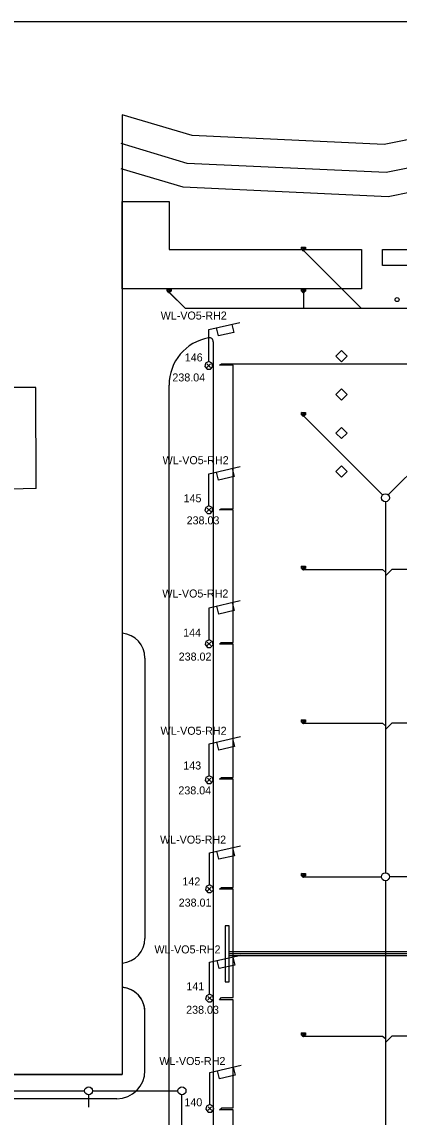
# Model space of a CAD drawing. Extents: x -264222 to -263592, y -1242345 to -1242048.
# Drawn here: x -263972 to -263924.9, y -1242184.8 to -1242047.9 of the extents above; entities that cross this region are included whole.
import ezdxf

# ---------------------------------------------------------------- set-up
doc = ezdxf.new("R2010")
doc.units = 0
for name, color, linetype in [('BOD_CISLO', 7, 'Continuous'), ('BOD_SYMBOL', 7, 'Continuous'), ('BOD_VYSKA', 7, 'Continuous'), ('KFA_2D_SITUACIA_DSP', 7, 'Continuous'), ('KFA_SO_62-1_VO_LAMPY_MERANE', 7, 'Continuous'), ('KFA_SO_62-1_VO_POPIS_LAMP_PROJEKT', 7, 'Continuous'), ('KFA_SO_62-1_VO_TRASA_KABLOV_PROJEKT', 7, 'Continuous'), ('RAM_NA_TLAC_1-500', 7, 'Continuous')]:
    doc.layers.add(name, color=color, linetype=linetype)

msp = doc.modelspace()

# ---------------------------------------------------------------- linework, layer by layer
at = {"layer": 'BOD_SYMBOL'}
for p, q in [((-263948.88, -1242091.1), (-263948.44, -1242090.66)), ((-263948.44, -1242091.1), (-263948.88, -1242090.66)), ((-263948.85, -1242109.12), (-263948.41, -1242108.68)), ((-263948.41, -1242109.12), (-263948.85, -1242108.68)), ((-263948.84, -1242125.86), (-263948.4, -1242125.42)), ((-263948.4, -1242125.86), (-263948.84, -1242125.42)), ((-263948.83, -1242142.86), (-263948.39, -1242142.42)), ((-263948.39, -1242142.86), (-263948.83, -1242142.42)), ((-263948.8, -1242156.5), (-263948.36, -1242156.05)), ((-263948.36, -1242156.5), (-263948.8, -1242156.05)), ((-263948.77, -1242170.15), (-263948.33, -1242169.71)), ((-263948.33, -1242170.15), (-263948.77, -1242169.71)), ((-263948.75, -1242183.93), (-263948.31, -1242183.49)), ((-263948.31, -1242183.93), (-263948.75, -1242183.49))]:
    msp.add_line(p, q, dxfattribs=at)
at = {"layer": 'KFA_2D_SITUACIA_DSP'}
for p, q in [((-263959.47, -1242059.53), (-263959.47, -1242179.48)), ((-263950.75, -1242062.15), (-263959.47, -1242059.53)), ((-263926.77, -1242063.25), (-263950.75, -1242062.15)), ((-263915.2, -1242060.92), (-263926.77, -1242063.25)), ((-263959.47, -1242071.38), (-263959.47, -1242070.38)), ((-263959.47, -1242070.38), (-263953.62, -1242070.38)), ((-263959.47, -1242076.38), (-263959.47, -1242071.38)), ((-263953.62, -1242070.38), (-263953.62, -1242076.38)), ((-263959.47, -1242081.31), (-263959.47, -1242076.38)), ((-263953.62, -1242076.38), (-263929.58, -1242076.38)), ((-263937.09, -1242076.38), (-263937.09, -1242076.09)), ((-263937.09, -1242076.09), (-263936.59, -1242076.09)), ((-263936.59, -1242076.38), (-263937.09, -1242076.09)), ((-263936.59, -1242076.38), (-263937.09, -1242076.09)), ((-263937.09, -1242076.09), (-263937.09, -1242076.38)), ((-263936.59, -1242076.38), (-263937.09, -1242076.38)), ((-263937.09, -1242076.38), (-263936.59, -1242076.38)), ((-263936.77, -1242076.55), (-263929.63, -1242083.7)), ((-263936.59, -1242076.09), (-263936.59, -1242076.38)), ((-263929.58, -1242076.38), (-263929.58, -1242081.31)), ((-263926.97, -1242076.38), (-263921.97, -1242076.38)), ((-263926.97, -1242078.38), (-263926.97, -1242076.38)), ((-263926.97, -1242076.38), (-263926.97, -1242076.38)), ((-263921.97, -1242078.38), (-263926.97, -1242078.38)), ((-263953.62, -1242081.31), (-263959.47, -1242081.31)), ((-263953.87, -1242081.6), (-263953.87, -1242081.31)), ((-263953.87, -1242081.31), (-263953.37, -1242081.31)), ((-263953.37, -1242081.6), (-263953.87, -1242081.31)), ((-263953.37, -1242081.6), (-263953.87, -1242081.31)), ((-263953.87, -1242081.31), (-263953.87, -1242081.6)), ((-263929.58, -1242081.31), (-263953.62, -1242081.31)), ((-263953.37, -1242081.31), (-263953.37, -1242081.6)), ((-263937.09, -1242081.6), (-263937.09, -1242081.31)), ((-263937.09, -1242081.31), (-263936.59, -1242081.31)), ((-263936.59, -1242081.6), (-263937.09, -1242081.31)), ((-263936.59, -1242081.6), (-263937.09, -1242081.31)), ((-263937.09, -1242081.31), (-263937.09, -1242081.6)), ((-263936.59, -1242081.31), (-263936.59, -1242081.6)), ((-263953.37, -1242081.6), (-263953.87, -1242081.6)), ((-263953.87, -1242081.6), (-263953.37, -1242081.6)), ((-263953.62, -1242081.7), (-263951.62, -1242083.7)), ((-263953.55, -1242081.77), (-263951.62, -1242083.7)), ((-263936.59, -1242081.6), (-263937.09, -1242081.6)), ((-263937.09, -1242081.6), (-263936.59, -1242081.6)), ((-263936.84, -1242081.8), (-263936.84, -1242083.7)), ((-263951.62, -1242083.7), (-263918.81, -1242083.7)), ((-263948.09, -1242087.9), (-263948.09, -1242241.46)), ((-263932.8, -1242089.71), (-263932.09, -1242089)), ((-263932.09, -1242089), (-263931.39, -1242089.71)), ((-263932.09, -1242089), (-263932.09, -1242089)), ((-263932.09, -1242090.41), (-263932.8, -1242089.71)), ((-263931.39, -1242089.71), (-263932.09, -1242090.41)), ((-263970.24, -1242093.63), (-263975.68, -1242093.61)), ((-263970.22, -1242106.22), (-263970.24, -1242093.63)), ((-263953.62, -1242244.46), (-263953.62, -1242093.31)), ((-263932.8, -1242094.51), (-263932.09, -1242093.8)), ((-263932.09, -1242095.21), (-263932.8, -1242094.51)), ((-263932.09, -1242093.8), (-263931.39, -1242094.51)), ((-263932.09, -1242093.8), (-263932.09, -1242093.8)), ((-263931.39, -1242094.51), (-263932.09, -1242095.21)), ((-263937.09, -1242097.05), (-263937.09, -1242096.76)), ((-263937.09, -1242096.76), (-263936.59, -1242096.76)), ((-263936.59, -1242097.05), (-263937.09, -1242096.76)), ((-263936.59, -1242097.05), (-263937.09, -1242096.76)), ((-263937.09, -1242096.76), (-263937.09, -1242097.05)), ((-263936.59, -1242097.05), (-263937.09, -1242097.05)), ((-263937.09, -1242097.05), (-263936.59, -1242097.05)), ((-263936.77, -1242097.22), (-263926.95, -1242107.05)), ((-263936.59, -1242096.76), (-263936.59, -1242097.05)), ((-263916.41, -1242097.22), (-263926.24, -1242107.05)), ((-263932.8, -1242099.31), (-263932.09, -1242098.6)), ((-263932.09, -1242098.6), (-263931.39, -1242099.31)), ((-263932.09, -1242098.6), (-263932.09, -1242098.6)), ((-263932.09, -1242100.01), (-263932.8, -1242099.31)), ((-263931.39, -1242099.31), (-263932.09, -1242100.01)), ((-263932.8, -1242104.11), (-263932.09, -1242103.4)), ((-263932.09, -1242104.81), (-263932.8, -1242104.11)), ((-263932.09, -1242103.4), (-263931.39, -1242104.11)), ((-263932.09, -1242103.4), (-263932.09, -1242103.4)), ((-263931.39, -1242104.11), (-263932.09, -1242104.81)), ((-263970.22, -1242106.22), (-263975.57, -1242106.38)), ((-263926.59, -1242107.9), (-263926.59, -1242154.25)), ((-263926.59, -1242107.9), (-263926.59, -1242154.25)), ((-263937.09, -1242116.25), (-263937.09, -1242115.96)), ((-263937.09, -1242115.96), (-263936.59, -1242115.96)), ((-263936.59, -1242116.25), (-263937.09, -1242115.96)), ((-263936.59, -1242116.25), (-263937.09, -1242115.96)), ((-263937.09, -1242115.96), (-263937.09, -1242116.25)), ((-263936.59, -1242116.25), (-263937.09, -1242116.25)), ((-263937.09, -1242116.25), (-263936.59, -1242116.25)), ((-263936.74, -1242116.35), (-263926.95, -1242116.35)), ((-263936.59, -1242115.96), (-263936.59, -1242116.25)), ((-263926.95, -1242116.35), (-263926.59, -1242116.68)), ((-263925.8, -1242116.35), (-263926.59, -1242117.15)), ((-263916.44, -1242116.35), (-263925.8, -1242116.35)), ((-263959.47, -1242124.32), (-263959.47, -1242124.32)), ((-263956.62, -1242127.42), (-263956.62, -1242162.45)), ((-263937.09, -1242135.45), (-263937.09, -1242135.16)), ((-263937.09, -1242135.16), (-263936.59, -1242135.16)), ((-263936.59, -1242135.45), (-263937.09, -1242135.16)), ((-263936.59, -1242135.45), (-263937.09, -1242135.16)), ((-263937.09, -1242135.16), (-263937.09, -1242135.45)), ((-263936.59, -1242135.45), (-263937.09, -1242135.45)), ((-263937.09, -1242135.45), (-263936.59, -1242135.45)), ((-263936.74, -1242135.55), (-263926.95, -1242135.55)), ((-263936.59, -1242135.16), (-263936.59, -1242135.45)), ((-263926.95, -1242135.55), (-263926.59, -1242135.88)), ((-263925.8, -1242135.55), (-263926.59, -1242136.35)), ((-263920.94, -1242135.55), (-263925.8, -1242135.55)), ((-263937.09, -1242154.65), (-263937.09, -1242154.36)), ((-263937.09, -1242154.36), (-263936.59, -1242154.36)), ((-263936.59, -1242154.65), (-263937.09, -1242154.36)), ((-263936.59, -1242154.65), (-263937.09, -1242154.36)), ((-263937.09, -1242154.36), (-263937.09, -1242154.65)), ((-263936.59, -1242154.65), (-263937.09, -1242154.65)), ((-263937.09, -1242154.65), (-263936.59, -1242154.65)), ((-263936.74, -1242154.75), (-263927.09, -1242154.75)), ((-263936.59, -1242154.36), (-263936.59, -1242154.65)), ((-263920.94, -1242154.75), (-263926.09, -1242154.75)), ((-263926.59, -1242155.25), (-263926.59, -1242204.25)), ((-263918.49, -1242164.13), (-263946.09, -1242164.13)), ((-263918.59, -1242164.38), (-263946.09, -1242164.38)), ((-263918.7, -1242164.63), (-263946.09, -1242164.63)), ((-263959.47, -1242165.55), (-263959.47, -1242165.55)), ((-263959.47, -1242168.58), (-263959.47, -1242168.58)), ((-263956.62, -1242178.98), (-263956.62, -1242171.65)), ((-263937.09, -1242174.55), (-263937.09, -1242174.26)), ((-263937.09, -1242174.26), (-263936.59, -1242174.26)), ((-263936.59, -1242174.55), (-263937.09, -1242174.26)), ((-263936.59, -1242174.55), (-263937.09, -1242174.26)), ((-263937.09, -1242174.26), (-263937.09, -1242174.55)), ((-263936.59, -1242174.26), (-263936.59, -1242174.55)), ((-263936.59, -1242174.55), (-263937.09, -1242174.55)), ((-263937.09, -1242174.55), (-263936.59, -1242174.55)), ((-263936.74, -1242174.65), (-263926.95, -1242174.65)), ((-263926.95, -1242174.65), (-263926.59, -1242174.98)), ((-263925.8, -1242174.65), (-263926.59, -1242175.45)), ((-263920.94, -1242174.65), (-263925.8, -1242174.65)), ((-264131.57, -1242179.48), (-263959.47, -1242179.48)), ((-263959.47, -1242179.48), (-264131.57, -1242179.48)), ((-263959.47, -1242179.48), (-264077.23, -1242179.48)), ((-263956.62, -1242178.98), (-263956.62, -1242178.98)), ((-263960.12, -1242182.48), (-264034.16, -1242182.48)), ((-264013.16, -1242181.5), (-263964.16, -1242181.5)), ((-263963.66, -1242182), (-263963.66, -1242183.53)), ((-263963.16, -1242181.5), (-263952.5, -1242181.5)), ((-263952, -1242222.53), (-263952, -1242182))]:
    msp.add_line(p, q, dxfattribs=at)
for points in [[(-263863.95, -1242065.11), (-263895.45, -1242062.32), (-263915.2, -1242060.92), (-263926.77, -1242063.25), (-263950.75, -1242062.15), (-263959.47, -1242059.53)], [(-263864.26, -1242068.59), (-263895.73, -1242065.81), (-263914.97, -1242064.45), (-263926.5, -1242066.77), (-263951.34, -1242065.63), (-263959.61, -1242063.14)], [(-263864.52, -1242071.58), (-263895.97, -1242068.8), (-263914.78, -1242067.47), (-263926.27, -1242069.78), (-263951.84, -1242068.6), (-263959.61, -1242066.28)], [(-263956.62, -1242178.98), (-263956.62, -1242171.63), (-263956.64, -1242171.26), (-263956.71, -1242170.89), (-263956.87, -1242170.41), (-263957.16, -1242169.89), (-263957.43, -1242169.55), (-263957.71, -1242169.29), (-263958.08, -1242169.02), (-263958.45, -1242168.83), (-263958.84, -1242168.69), (-263959.06, -1242168.64), (-263959.27, -1242168.6), (-263959.47, -1242168.58)]]:
    msp.add_lwpolyline(points, dxfattribs=at)
msp.add_lwpolyline([(-263946.09, -1242167.88), (-263946.09, -1242160.88), (-263946.59, -1242160.88), (-263946.59, -1242167.88)], close=True, dxfattribs=at)
for centre, radius in [((-263936.84, -1242076.48), 0.1), ((-263953.62, -1242081.7), 0.1), ((-263936.84, -1242081.7), 0.1), ((-263925.14, -1242082.64), 0.25), ((-263936.84, -1242097.15), 0.1), ((-263926.59, -1242107.4), 0.5), ((-263936.84, -1242116.35), 0.1), ((-263936.84, -1242135.55), 0.1), ((-263936.84, -1242154.75), 0.1), ((-263926.59, -1242154.75), 0.5), ((-263936.84, -1242174.65), 0.1), ((-263963.66, -1242181.5), 0.5), ((-263952, -1242181.5), 0.5)]:
    msp.add_circle(centre, radius, dxfattribs=at)
for centre, radius, start, end in [((-263947.63, -1242093.3), 5.98, 100.0694, 180.066), ((-263948.59, -1242087.9), 0.5, 0, 100.0694), ((-263959.74, -1242127.43), 3.12, 0.1518, 85.0363), ((-263959.74, -1242162.44), 3.12, 274.9637, 359.8482), ((-263959.67, -1242171.63), 3.05, 359.6441, 86.2155), ((-263960.12, -1242178.98), 3.5, 270, 0)]:
    msp.add_arc(centre, radius, start, end, dxfattribs=at)
at = {"layer": 'KFA_SO_62-1_VO_LAMPY_MERANE'}
for p, q in [((-263948.71, -1242090.88), (-263948.61, -1242090.88)), ((-263948.66, -1242090.88), (-263948.66, -1242090.88)), ((-263948.68, -1242108.9), (-263948.58, -1242108.9)), ((-263948.63, -1242108.9), (-263948.63, -1242108.9)), ((-263948.67, -1242125.64), (-263948.57, -1242125.64)), ((-263948.62, -1242125.64), (-263948.62, -1242125.64)), ((-263948.66, -1242142.64), (-263948.56, -1242142.64)), ((-263948.61, -1242142.64), (-263948.61, -1242142.64)), ((-263948.63, -1242156.27), (-263948.53, -1242156.27)), ((-263948.58, -1242156.27), (-263948.58, -1242156.27)), ((-263948.6, -1242169.93), (-263948.5, -1242169.93)), ((-263948.55, -1242169.93), (-263948.55, -1242169.93)), ((-263948.58, -1242183.71), (-263948.48, -1242183.71)), ((-263948.53, -1242183.71), (-263948.53, -1242183.71))]:
    msp.add_line(p, q, dxfattribs=at)
for points in [[(-263948.66, -1242090.38), (-263949.06, -1242090.58), (-263949.16, -1242090.98), (-263948.86, -1242091.33), (-263948.46, -1242091.33), (-263948.16, -1242090.98), (-263948.26, -1242090.58), (-263948.66, -1242090.38), (-263948.66, -1242086.38), (-263944.76, -1242085.48)], [(-263945.76, -1242085.73), (-263945.51, -1242086.73), (-263947.46, -1242087.18), (-263947.71, -1242086.18)], [(-263948.63, -1242108.4), (-263949.03, -1242108.6), (-263949.13, -1242109), (-263948.83, -1242109.35), (-263948.43, -1242109.35), (-263948.13, -1242109), (-263948.23, -1242108.6), (-263948.63, -1242108.4), (-263948.63, -1242104.4), (-263944.73, -1242103.5)], [(-263945.73, -1242103.75), (-263945.48, -1242104.75), (-263947.43, -1242105.2), (-263947.68, -1242104.2)], [(-263948.62, -1242125.14), (-263949.02, -1242125.34), (-263949.12, -1242125.74), (-263948.82, -1242126.09), (-263948.42, -1242126.09), (-263948.12, -1242125.74), (-263948.22, -1242125.34), (-263948.62, -1242125.14), (-263948.62, -1242121.14), (-263944.72, -1242120.24)], [(-263945.72, -1242120.49), (-263945.47, -1242121.49), (-263947.42, -1242121.94), (-263947.67, -1242120.94)], [(-263948.61, -1242142.14), (-263949.01, -1242142.34), (-263949.11, -1242142.74), (-263948.81, -1242143.09), (-263948.41, -1242143.09), (-263948.11, -1242142.74), (-263948.21, -1242142.34), (-263948.61, -1242142.14), (-263948.61, -1242138.14), (-263944.71, -1242137.24)], [(-263945.71, -1242137.49), (-263945.46, -1242138.49), (-263947.41, -1242138.94), (-263947.66, -1242137.94)], [(-263948.58, -1242155.77), (-263948.98, -1242155.97), (-263949.08, -1242156.37), (-263948.78, -1242156.72), (-263948.38, -1242156.72), (-263948.08, -1242156.37), (-263948.18, -1242155.97), (-263948.58, -1242155.77), (-263948.58, -1242151.77), (-263944.68, -1242150.87)], [(-263945.68, -1242151.12), (-263945.43, -1242152.12), (-263947.38, -1242152.57), (-263947.63, -1242151.57)], [(-263948.55, -1242169.43), (-263948.95, -1242169.63), (-263949.05, -1242170.03), (-263948.75, -1242170.38), (-263948.35, -1242170.38), (-263948.05, -1242170.03), (-263948.15, -1242169.63), (-263948.55, -1242169.43), (-263948.55, -1242165.43), (-263944.65, -1242164.53)], [(-263945.65, -1242164.78), (-263945.4, -1242165.78), (-263947.35, -1242166.23), (-263947.6, -1242165.23)], [(-263948.53, -1242183.21), (-263948.93, -1242183.41), (-263949.03, -1242183.81), (-263948.73, -1242184.16), (-263948.33, -1242184.16), (-263948.03, -1242183.81), (-263948.13, -1242183.41), (-263948.53, -1242183.21), (-263948.53, -1242179.21), (-263944.63, -1242178.31)], [(-263945.63, -1242178.56), (-263945.38, -1242179.56), (-263947.33, -1242180.01), (-263947.58, -1242179.01)]]:
    msp.add_lwpolyline(points, dxfattribs=at)
at = {"layer": 'KFA_SO_62-1_VO_TRASA_KABLOV_PROJEKT'}
for p, q in [((-263947.31, -1242090.84), (-263947.08, -1242090.66)), ((-263945.59, -1242090.84), (-263947.31, -1242090.84)), ((-263947.08, -1242090.66), (-263917.77, -1242090.66)), ((-263945.59, -1242108.76), (-263945.59, -1242090.84)), ((-263947.32, -1242108.91), (-263947.11, -1242108.76)), ((-263945.59, -1242108.91), (-263947.32, -1242108.91)), ((-263947.11, -1242108.76), (-263945.59, -1242108.76)), ((-263945.59, -1242125.49), (-263945.59, -1242108.91)), ((-263947.3, -1242125.71), (-263947.1, -1242125.49)), ((-263945.59, -1242125.71), (-263947.3, -1242125.71)), ((-263947.1, -1242125.49), (-263945.59, -1242125.49)), ((-263945.59, -1242142.34), (-263945.59, -1242125.71)), ((-263947.31, -1242142.55), (-263947.05, -1242142.34)), ((-263945.59, -1242142.55), (-263947.31, -1242142.55)), ((-263947.05, -1242142.34), (-263945.59, -1242142.34)), ((-263945.59, -1242156.1), (-263945.59, -1242142.55)), ((-263947.31, -1242156.31), (-263947.08, -1242156.1)), ((-263945.6, -1242156.31), (-263947.31, -1242156.31)), ((-263947.08, -1242156.1), (-263945.59, -1242156.1)), ((-263945.6, -1242169.85), (-263945.6, -1242156.31)), ((-263947.31, -1242170.12), (-263947.06, -1242169.85)), ((-263945.6, -1242170.12), (-263947.31, -1242170.12)), ((-263947.06, -1242169.85), (-263945.6, -1242169.85)), ((-263945.6, -1242183.62), (-263945.6, -1242170.12)), ((-263947.3, -1242183.86), (-263947.01, -1242183.62)), ((-263945.59, -1242183.86), (-263947.3, -1242183.86)), ((-263947.01, -1242183.62), (-263945.6, -1242183.62)), ((-263945.59, -1242200.46), (-263945.59, -1242183.86))]:
    msp.add_line(p, q, dxfattribs=at)
at = {"layer": 'RAM_NA_TLAC_1-500'}
msp.add_lwpolyline([(-264221.9, -1242344.94), (-263591.9, -1242344.94), (-263591.9, -1242047.94), (-264221.9, -1242047.94)], close=True, dxfattribs=at)

# ---------------------------------------------------------------- texts
at = {"layer": 'BOD_CISLO'}
for s, p in [('146', (-263951.65, -1242090.36)), ('145', (-263951.8, -1242107.96)), ('144', (-263951.85, -1242124.74)), ('143', (-263951.84, -1242141.35)), ('142', (-263951.95, -1242155.84)), ('141', (-263951.45, -1242168.94)), ('140', (-263951.7, -1242183.43))]:
    msp.add_text(s, height=1, dxfattribs=at).set_placement(p)
at = {"layer": 'BOD_VYSKA'}
for s, p in [('238.04', (-263953.2, -1242092.86)), ('238.03', (-263951.42, -1242110.72)), ('238.02', (-263952.41, -1242127.74)), ('238.04', (-263952.45, -1242144.46)), ('238.01', (-263952.41, -1242158.48)), ('238.03', (-263951.48, -1242171.87))]:
    msp.add_text(s, height=1, dxfattribs=at).set_placement(p)
at = {"layer": 'KFA_SO_62-1_VO_POPIS_LAMP_PROJEKT'}
for p in [(-263954.66, -1242085.13), (-263954.42, -1242103.2), (-263954.46, -1242119.86), (-263954.68, -1242137.01), (-263954.74, -1242150.61), (-263955.44, -1242164.33), (-263954.83, -1242178.27)]:
    msp.add_text('WL-VO5-RH2', height=1, dxfattribs=at).set_placement(p)

doc.saveas('drawing.dxf')
